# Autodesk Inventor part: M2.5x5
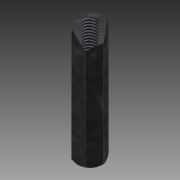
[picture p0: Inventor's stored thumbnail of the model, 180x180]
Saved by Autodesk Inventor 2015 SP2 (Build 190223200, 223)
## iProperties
Created: 2012-08
Part Number: M2.5x5
Material: Stahl
Document SubType Name: Modeling
Designer: rYan
Density: 7.85 g/cm^3
Mass: 3.36246 g
Surface Area: 5.74911 cm^2
Volume: 0.428339 cm^3
Appearance: Platte
Author: rYan
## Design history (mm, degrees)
derived "Abstandsbolzen Typ A.ipt"
feature "Volumenkörper1::Abstandsbolzen Typ A.ipt"
tag "Bezeichnung1"
node "Volumenkörper1"
other parameters: "SW" = 4, "d2" = 0, "d16" = 45 deg
